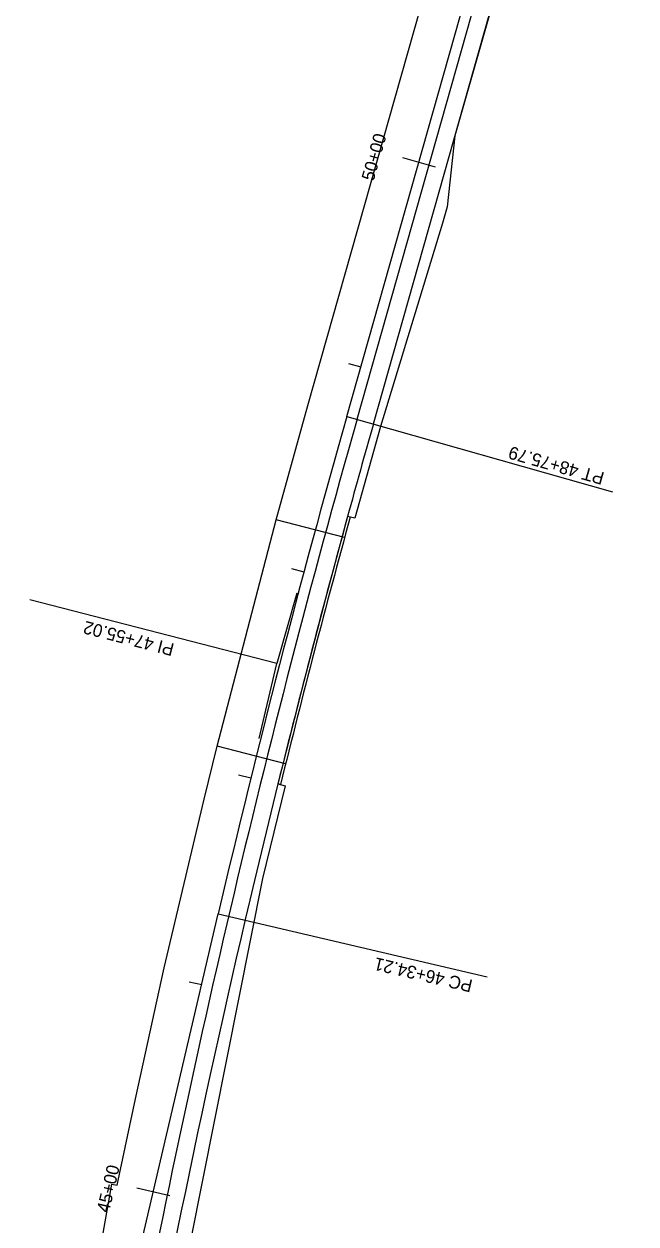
# Model space of a CAD drawing. Extents: x 1445613 to 1446340, y 2042797 to 2056486.
# Drawn here: x 1445758 to 1446046, y 2054340 to 2054904 of the extents above; entities that cross this region are included whole.
import ezdxf

# ---------------------------------------------------------------- set-up
doc = ezdxf.new("R2010")
doc.units = 0
for name, color, linetype in [('20', 7, 'Continuous'), ('R_Bridge', 7, 'Continuous'), ('R_Horz Alg', 7, 'Continuous'), ('R_Horz Alg Annot_Detour', 7, 'Continuous'), ('R_Horz Alg Stationing_Detour', 7, 'Continuous'), ('R_Proposed Road', 7, 'Continuous')]:
    doc.layers.add(name, color=color, linetype=linetype)

msp = doc.modelspace()

# ---------------------------------------------------------------- linework, layer by layer
at = {"layer": '20'}
for points in [[(1445780.04, 2054251.75), (1445799.01, 2054359.02), (1445801.56, 2054358.48), (1445810.13, 2054399.1), (1445823.75, 2054460.64), (1445842.46, 2054539.94), (1445848.63, 2054564.93), (1445876.38, 2054671.37), (1445891.32, 2054725.14), (1446014.88, 2055160.82)], [(1445983.88, 2054934.25), (1445960.45, 2054851.81), (1445956.75, 2054818.56), (1445954.6, 2054810.84), (1445925.39, 2054715.18), (1445913.37, 2054672.07), (1445909.98, 2054672.95), (1445899.56, 2054634.37), (1445888.42, 2054591.74), (1445881.03, 2054562.61), (1445877.18, 2054547.13), (1445880.57, 2054546.25), (1445870.01, 2054502.76), (1445836.06, 2054332.52)]]:
    msp.add_lwpolyline(points, dxfattribs=at)
at = {"layer": 'R_Bridge'}
for p, q in [((1445911.19, 2054672.64), (1445909.98, 2054672.95)), ((1445908.55, 2054662.98), (1445876.38, 2054671.37)), ((1445880.8, 2054556.54), (1445848.63, 2054564.93)), ((1445878.39, 2054546.82), (1445877.18, 2054547.13))]:
    msp.add_line(p, q, dxfattribs=at)
for radius, start, end in [(5171.21, 164.66655, 166.10725), (5169.96, 164.66637, 166.10743)]:
    msp.add_arc((1450897.11, 2053305.5), radius, start, end, dxfattribs=at)
at = {"layer": 'R_Horz Alg'}
for p, q in [((1445909.6, 2054719.96), (1446033.15, 2055155.64)), ((1445757.73, 2054095.33), (1445849.12, 2054486.09))]:
    msp.add_line(p, q, dxfattribs=at)
msp.add_arc((1450897.11, 2053305.5), 5184.21, 164.16667, 166.83661, dxfattribs=at)
at = {"layer": 'R_Horz Alg Annot_Detour'}
for p in [(1445886.05, 2054636.93), (1445868.42, 2054568.59)]:
    msp.add_line(p, (1445876.63, 2054603.73), dxfattribs=at)
for points in [[(1445909.6, 2054719.96), (1446034.66, 2054684.49)], [(1445876.63, 2054603.73), (1445760.46, 2054633.77)], [(1445849.12, 2054486.09), (1445975.71, 2054456.49)]]:
    msp.add_lwpolyline(points, dxfattribs=at)
at = {"layer": 'R_Horz Alg Stationing_Detour'}
for points in [[(1445935.79, 2054841.64), (1445951.18, 2054837.27)], [(1445910.43, 2054744.88), (1445916.2, 2054743.25)], [(1445883.66, 2054648.45), (1445889.45, 2054646.89)], [(1445858.68, 2054551.49), (1445864.51, 2054550.05)], [(1445835.49, 2054454.15), (1445841.33, 2054452.78)], [(1445810.77, 2054357.23), (1445826.35, 2054353.58)]]:
    msp.add_lwpolyline(points, dxfattribs=at)
at = {"layer": 'R_Proposed Road'}
for p, q in [((1445914.41, 2054718.59), (1446037.96, 2055154.27)), ((1445922.1, 2054716.41), (1446045.66, 2055152.09))]:
    msp.add_line(p, q, dxfattribs=at)
for radius, start, end in [(5179.21, 164.16667, 169.4239), (5171.21, 164.16667, 164.66655), (5171.21, 166.10725, 169.4239)]:
    msp.add_arc((1450897.11, 2053305.5), radius, start, end, dxfattribs=at)

# ---------------------------------------------------------------- texts
at = {"layer": 'R_Horz Alg Annot_Detour'}
for s, rotation, p in [('PT 48+75.79', 164.1667, (1446031.18, 2054693.48)), ('PI 47+55.02', 165.5016, (1445828.8, 2054613)), ('PC 46+34.21', 166.8366, (1445969.18, 2054454.93))]:
    msp.add_text(s, height=6, rotation=rotation, dxfattribs=at).set_placement(p)
at = {"layer": 'R_Horz Alg Stationing_Detour'}
for s, rotation, p in [('50+00', 74.1667, (1445922.17, 2054830.27)), ('45+00', 76.8366, (1445797.7, 2054345.25))]:
    msp.add_text(s, height=6, rotation=rotation, dxfattribs=at).set_placement(p)

doc.saveas('drawing.dxf')
